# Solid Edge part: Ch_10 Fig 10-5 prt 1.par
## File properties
Author: Robert a Rhodes jr
Template: NORMENG.PAR
Last saved by: Cadcim
Revision: 6
Application: Solid Edge
Accuracy: 0.99
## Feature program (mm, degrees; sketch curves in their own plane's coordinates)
sketch for "unnamed Protrusion 1" plane through (0, 0, 0) normal (0, 0, 1) x-axis (1, 0, 0)
  line (-25.2008, 3.175) -> (-20.6375, 3.175)
  arc centre (-20.6375, 0) radius 3.175 from (-20.6375, 3.175) to (-20.6375, -3.175) cw
  line (-25.2008, -3.175) -> (-20.6375, -3.175)
  arc centre (0, 0) radius 25.4 from (-3.175, -25.2008) to (-25.2008, -3.175) cw
  line (-3.175, -25.2008) -> (-3.175, -20.6375)
  arc centre (0, -20.6375) radius 3.175 from (-3.175, -20.6375) to (3.175, -20.6375) cw
  line (3.175, -25.2008) -> (3.175, -20.6375)
  arc centre (0, 0) radius 25.4 from (25.2008, -3.175) to (3.175, -25.2008) cw
  line (25.2008, -3.175) -> (20.6375, -3.175)
  arc centre (20.6375, 0) radius 3.175 from (20.6375, -3.175) to (20.6375, 3.175) cw
  line (25.2008, 3.175) -> (20.6375, 3.175)
  arc centre (0, 0) radius 25.4 from (3.175, 25.2008) to (25.2008, 3.175) cw
  line (3.175, 25.2008) -> (3.175, 20.6375)
  arc centre (0, 20.6375) radius 3.175 from (3.175, 20.6375) to (-3.175, 20.6375) cw
  line (-3.175, 25.2008) -> (-3.175, 20.6375)
  arc centre (0, 0) radius 25.4 from (-25.2008, 3.175) to (-3.175, 25.2008) cw
extrude "unnamed Protrusion 1" add finite 3.175 along +normal
sketch for "Hole_1" plane through (0, 0, 3.175) normal (0, 0, 1) x-axis (1, 0, 0)
  hole centre (0, 0) bore radius 12.7
hole "Hole_1" diameter 25.4 through
sketch for "ExtrudedProtrusion_2" plane through (0, 0, 3.175) normal (0, 0, 1) x-axis (1, 0, 0)
extrude "ExtrudedProtrusion_2" add finite 15.875 along +normal
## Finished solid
Body 1: solid body, 22 faces, 52 edges, 32 vertices.
  Faces by surface: plane 12, cylinder 10
  Edges by curve: line 32, circle 20
Bounding box of the edges (mm): 50.402 x 50.402 x 19.050, from (-25.2008, -25.2008, 0) to (25.2008, 25.2008, 19.05).
Cylindrical faces by radius (mm): R3.175 x4, R12.7 x1, R15.3815 x1, R25.4 x4
Planar faces by outward normal: +x 2, +y 2, +z 2, -x 2, -y 2, -z 2
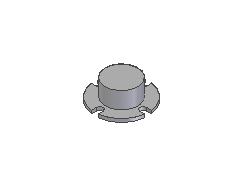
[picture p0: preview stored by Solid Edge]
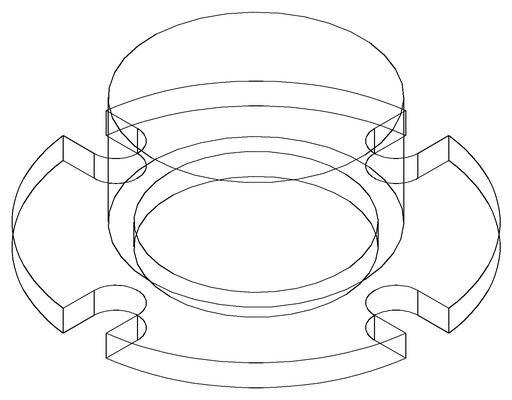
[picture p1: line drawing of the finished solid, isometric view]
